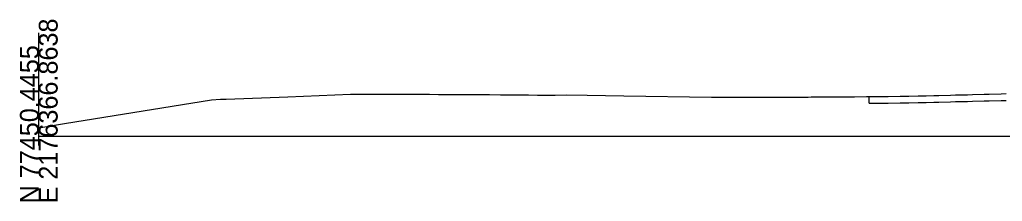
# Model space of a CAD drawing. Extents: x 2177029 to 2201446, y 59897 to 78390.
# Drawn here: x 2200039.9 to 2200185.8, y 62397.6 to 62424.6 of the extents above; entities that cross this region are included whole.
import ezdxf

# ---------------------------------------------------------------- set-up
doc = ezdxf.new("R2010")
doc.units = 0
for name, color, linetype in [('Exist Cross Section Cell', 7, 'Continuous'), ('Exist XS Ground Line', 7, 'Continuous'), ('Old_Level_3', 7, 'Continuous'), ('Prop CMT Pvmt Wedge Surface 1', 7, 'Continuous'), ('Prop CMT Top Wall Envelope', 7, 'Continuous')]:
    doc.layers.add(name, color=color, linetype=linetype)

msp = doc.modelspace()

# ---------------------------------------------------------------- linework, layer by layer
at = {"layer": 'Exist Cross Section Cell'}
msp.add_line((2200042.73, 62407.31), (2200242.73, 62407.31), dxfattribs=at)
at = {"layer": 'Exist XS Ground Line'}
msp.add_lwpolyline([(2200042.73, 62408.53), (2200046.53, 62409.17), (2200068.39, 62412.73), (2200069.71, 62412.79), (2200070.57, 62412.82), (2200079.69, 62413.17), (2200089.01, 62413.53), (2200090.47, 62413.57), (2200091.89, 62413.57), (2200094.6, 62413.57), (2200095.02, 62413.56), (2200097.1, 62413.55), (2200098.28, 62413.55), (2200099.46, 62413.54), (2200100.25, 62413.53), (2200100.74, 62413.53), (2200102.07, 62413.52), (2200103.67, 62413.52), (2200104.26, 62413.52), (2200105.71, 62413.51), (2200106.6, 62413.5), (2200107.57, 62413.5), (2200109.12, 62413.49), (2200109.62, 62413.49), (2200111.26, 62413.47), (2200112.52, 62413.46), (2200113.09, 62413.45), (2200114.07, 62413.45), (2200114.92, 62413.44), (2200115.42, 62413.44), (2200116.74, 62413.42), (2200118.58, 62413.41), (2200119.03, 62413.4), (2200119.38, 62413.41), (2200121.01, 62413.45), (2200124.13, 62413.39), (2200129.6, 62413.29), (2200142.6, 62413.12), (2200143.64, 62413.1), (2200144.16, 62413.1), (2200145.08, 62413.1), (2200146.48, 62413.1), (2200147.99, 62413.09), (2200149.3, 62413.09), (2200150.51, 62413.1), (2200152.11, 62413.11), (2200153.34, 62413.12), (2200154.61, 62413.12), (2200155.09, 62413.13), (2200156.07, 62413.13), (2200156.96, 62413.13), (2200157.4, 62413.14), (2200158.82, 62413.14), (2200160.19, 62413.15), (2200160.69, 62413.15), (2200161.68, 62413.16), (2200163.08, 62413.17), (2200163.81, 62413.17), (2200165.58, 62413.19), (2200166.31, 62413.2), (2200168.08, 62413.22), (2200168.82, 62413.23), (2200170.58, 62413.24), (2200171.89, 62413.26), (2200173.28, 62413.29), (2200174.44, 62413.32), (2200175.58, 62413.35), (2200176.33, 62413.37), (2200178.08, 62413.42), (2200178.83, 62413.44), (2200180.58, 62413.47), (2200181.33, 62413.5), (2200183.08, 62413.55), (2200183.83, 62413.56), (2200185.58, 62413.6), (2200186.34, 62413.63)], dxfattribs=at)
at = {"layer": 'Old_Level_3'}
msp.add_line((2200042.73, 62405.94), (2200042.73, 62422.68), dxfattribs=at)
at = {"layer": 'Prop CMT Pvmt Wedge Surface 1'}
for p, q in [((2200166.01, 62412.2), (2200166.01, 62413.2)), ((2200166.01, 62412.2), (2200166.31, 62412.2)), ((2200166.31, 62412.2), (2200168.08, 62412.22)), ((2200168.08, 62412.22), (2200168.82, 62412.23)), ((2200168.82, 62412.23), (2200170.58, 62412.24)), ((2200170.58, 62412.24), (2200171.89, 62412.26)), ((2200171.89, 62412.26), (2200173.28, 62412.29)), ((2200173.28, 62412.29), (2200174.44, 62412.32)), ((2200174.44, 62412.32), (2200175.58, 62412.35)), ((2200175.58, 62412.35), (2200176.33, 62412.37)), ((2200176.33, 62412.37), (2200178.08, 62412.42)), ((2200178.08, 62412.42), (2200178.83, 62412.44)), ((2200178.83, 62412.44), (2200180.58, 62412.47)), ((2200180.58, 62412.47), (2200181.33, 62412.5)), ((2200181.33, 62412.5), (2200183.08, 62412.55)), ((2200183.08, 62412.55), (2200183.83, 62412.56)), ((2200183.83, 62412.56), (2200185.58, 62412.6)), ((2200185.58, 62412.6), (2200186.34, 62412.63))]:
    msp.add_line(p, q, dxfattribs=at)

# ---------------------------------------------------------------- texts
at = {"layer": 'Exist Cross Section Cell'}
for s, p in [('E 2176366.8638', (2200045.53, 62397.31)), ('N 77450.4455', (2200042.73, 62397.31))]:
    msp.add_text(s, height=2.8, rotation=90, dxfattribs=at).set_placement(p)
at = {"layer": 'Prop CMT Top Wall Envelope'}
msp.add_text('-', height=0.0001, dxfattribs=at).set_placement((2200042.73, 62407.31))
msp.add_text('-', height=0.0001, dxfattribs=at).set_placement((2200042.73, 62407.31))

doc.saveas('drawing.dxf')
